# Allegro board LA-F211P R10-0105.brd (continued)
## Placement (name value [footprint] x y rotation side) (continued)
PL606  HCB2012KF-121T50_0805  [TAI-T_HCB2012KF-121T50_2P]  59.12 105.24 0 top
PL607  1UH_MMD-05CZ-1R0M-M7L_7A_20%  [MAGLA_MMD-05CZ-1R0M-M7L_2P]  70.41 104.86 0 bottom
PL608  HCB2012KF-121T50_0805  [TAI-T_HCB2012KF-121T50_2P]  132.04 23.26 180 bottom
PL609  HCB2012KF-121T50_0805  [TAI-T_HCB2012KF-121T50_2P]  59.53 74.39 90 bottom
PL700  HCB2012KF-121T50_0805  [TAI-T_HCB2012KF-121T50_2P]  6.82 55.5 270 bottom
PL701  1UH_MLD-06CZH1R0M-N1L_11.3A_20%  [MAG_MLD-06CZH1R0M-N1L_2P]  11.76 45.91 270 bottom
PL800  1UH_MMD-05CZ-1R0M-M7L_7A_20%  [MAGLA_MMD-05CZ-1R0M-M7L_2P]  81.09 99.81 54.9 bottom
PL801  HCB2012KF-121T50_0805  [TAI-T_HCB2012KF-121T50_2P]  82.87 91.11 180 bottom
PL900  HCB2012KF-121T50_0805  [TAI-T_HCB2012KF-121T50_2P]  18.56 20.29 0 top
PL901  1UH_HEI322512A-1R0M-Q8_3.7A_20%  [CHILI_HEI322512A-1R0M-Q8_2P]  24.23 20.94 90 top
PL1000  BLM15PX121SN1D_2P  [MURAT_BLM15PX121SN1D_2P]  98.75 28.75 270 top
PL1001  1UH_MMD-05CZ-1R0M-M7L_7A_20%  [MAGLA_MMD-05CZ-1R0M-M7L_2P]  102.78 38.67 90 bottom
PL1200  0.15UH_HPPC06030-R15M-Q8_35A_20%  [L_7X7X3_M]  115.93 40.3 90 bottom
PL1201  HCB2012KF-121T50_0805  [TAI-T_HCB2012KF-121T50_2P]  137.45 31.5 180 bottom
PL1202  HCB2012KF-121T50_0805  [TAI-T_HCB2012KF-121T50_2P]  137.45 33.28 180 bottom
PL1203  0.15UH_HPPC06030-R15M-Q8_35A_20%  [L_7X7X3_M]  123.49 40.28 90 bottom
PL1204  0.15UH_HPPC06030-R15M-Q8_35A_20%  [L_7X7X3_M]  131.05 41.85 90 bottom
PL1300  HCB2012KF-121T50_0805  [TAI-T_HCB2012KF-121T50_2P]  151.24 47.21 90 bottom
PL1301  0.15UH_HPPC06030-R15M-Q8_35A_20%  [L_7X7X3_M]  144.05 54.08 180 bottom
PL1302  HCB2012KF-121T50_0805  [TAI-T_HCB2012KF-121T50_2P]  149.44 47.21 90 bottom
PL1303  0.15UH_HPPC06030-R15M-Q8_35A_20%  [L_7X7X3_M]  144.42 64.86 180 bottom
PL1304  HCB2012KF-121T50_0805  [TAI-T_HCB2012KF-121T50_2P]  107.25 32.01 90 bottom
PL1305  0.33UH_MMD-05CZ-R33M-V1L_13.7A_20%  [MAG_MMD-05CZ-R33M-V1L_2P]  109.32 40.96 90 bottom
PL1500  HCB2012KF-121T50_0805  [TAI-T_HCB2012KF-121T50_2P]  70.57 80.55 270 bottom
PL1501  1UH_HEI322512A-1R0M-Q8_3.7A_20%  [CHILI_HEI322512A-1R0M-Q8_2P]  66.62 76.46 180 bottom
PL1900  HCB2012KF-121T50_0805  [TAI-T_HCB2012KF-121T50_2P]  104.73 33.43 180 bottom
PL1901  HCB2012KF-121T50_0805  [TAI-T_HCB2012KF-121T50_2P]  104.74 31.63 180 bottom
PL1902  0.22UH_MMD-06DZER22MEM2L__32A_20%  [L_7X7X4_M]  87.17 41.35 90 bottom
PL1904  0.22UH_MMD-06DZER22MEM2L__32A_20%  [L_7X7X4_M]  71.08 41.39 90 bottom
PL2001  0.22UH_MMD-06DZER22MEM2L__32A_20%  [L_7X7X4_M]  79.18 41.39 90 bottom
PL2200  HCB2012KF-121T50_0805  [TAI-T_HCB2012KF-121T50_2P]  54.66 62.9 0 top
PL2201  0.33UH 20% MMD-05CZ-R33MER1L 13.7A  [MAG_MMD05CZR47M_4P]  64.6 58.76 0 bottom
PL2202  0.22UH_MMD-06DZER22MEM2L__32A_20%  [L_7X7X4_M]  95.91 41.33 90 bottom
PL2203  1UH_HEI322512A-1R0M-Q8_3.7A_20%  [CHILI_HEI322512A-1R0M-Q8_2P]  68.09 51.3 0 bottom
PL2204  HCB2012KF-121T50_0805  [TAI-T_HCB2012KF-121T50_2P]  64.15 52.71 270 top
PL2205  HCB2012KF-121T50_0805  [TAI-T_HCB2012KF-121T50_2P]  145.44 94.1 270 bottom
PL2207  1UH_MMD-05AB-1R0M-V1L_4.4A_20%  [MAG_MMD-05AB-1R0M-V1L_2P]  148.74 85.94 270 bottom
PQ100  AON7401_DFN8-5  [AON7405_DFN8-5]  16.61 74.8 0 bottom
PQ101  S TR AO7401 1P SC70-3  [SI1303DL-T1-E3_SOT323-3]  21.04 77.35 90 top
PQ102  -  [AON7405_DFN8-5]  13.69 70.07 0 bottom
PQ103  -  [AON7405_DFN8-5]  19.59 64.84 180 bottom
PQ105  S TR AO7401 1P SC70-3  [SI1303DL-T1-E3_SOT323-3]  23.53 77.84 180 top
PQ106  S TR AO7401 1P SC70-3  [SI1303DL-T1-E3_SOT323-3]  24.13 71.44 270 top
PQ111  AON7401_DFN8-5  [AON7405_DFN8-5]  22.35 99.87 90 bottom
PQ112  S TR AO7401 1P SC70-3  [SI1303DL-T1-E3_SOT323-3]  22.26 96.67 180 top
PQ113  -  [AON7405_DFN8-5]  22.35 96.06 90 bottom
PQ114  -  [AON7405_DFN8-5]  24.33 94.23 270 bottom
PQ116  S TR AO7401 1P SC70-3  [SI1303DL-T1-E3_SOT323-3]  19.34 100.06 0 top
PQ117  S TR AO7401 1P SC70-3  [SI1303DL-T1-E3_SOT323-3]  26.29 91.43 0 top
PQ132  -  [L2N7002WT1G_SC70-3]  39.72 98.28 180 bottom
PQ133  -  [L2N7002WT1G_SC70-3]  37.16 98.34 180 bottom
PQ134  -  [L2N7002WT1G_SC70-3]  17.92 74.03 180 top
PQ136  -  [2N7002KDW_SOT363-6]  28.89 70.63 90 top
PQ137  -  [L2N7002WT1G_SC70-3]  39.95 94.77 0 top
PQ139  -  [2N7002KDW_SOT363-6]  37.1 95.33 90 top
PQ143  -  [L2N7002WT1G_SC70-3]  22.21 74.79 180 top
PQ144  -  [L2N7002WT1G_SC70-3]  19.61 95.23 180 top
PQ146  -  [2N7002KDW_SOT363-6]  30.52 102.11 90 bottom
PQ147  -  [2N7002KDW_SOT363-6]  35.29 104.03 180 bottom
PQ149  -  [2N7002KDW_SOT363-6]  34.39 100.17 270 top
PQ150  -  [2N7002KDW_SOT363-6]  30.56 106.51 0 bottom
PQ152  -  [2N7002KDW_SOT363-6]  42.01 104.4 0 top
PQ153  -  [2N7002KDW_SOT363-6]  35.21 99.41 270 bottom
PQ154  -  [2N7002KDW_SOT363-6]  31.66 96.9 90 top
PQ155  -  [2N7002KDW_SOT363-6]  27.34 76.23 270 top
PQ199  -  [L2N7002WT1G_SC70-3]  33.54 72.45 90 top
PQ200  PJC138K_SOT-323  [RJU003N03_UMT3]  34.26 96.83 180 bottom
PQ201  PJC138K_SOT-323  [RJU003N03_UMT3]  36.8 96.83 180 bottom
PQ202  PJC138K_SOT-323  [RJU003N03_UMT3]  39.34 96.83 180 bottom
PQ203  PJC138K_SOT-323  [RJU003N03_UMT3]  45.84 96.81 180 top
PQ204  PJC138K_SOT-323  [RJU003N03_UMT3]  43.3 97.59 180 top
PQ205  PJC138K_SOT-323  [RJU003N03_UMT3]  45.2 100.95 90 top
PQ213  -  [L2N7002WT1G_SC70-3]  38.2 103.9 0 top
PQ216  -  [2N7002KDW_SOT363-6]  19.77 69.74 0 top
PQ217  -  [2N7002KDW_SOT363-6]  22.16 91.02 0 top
PQ322  -  [L2N7002WT1G_SC70-3]  49.67 72.47 270 top
PQ325  S TR AO7401 1P SC70-3  [SI1303DL-T1-E3_SOT323-3]  47.41 65.97 270 top
PQ328  S TR AO7401 1P SC70-3  [SI1303DL-T1-E3_SOT323-3]  47.98 68.15 0 top
PQ330  -  [2N7002KDW_SOT363-6]  50.07 68.03 0 top
PQ500  -  [AON7405_DFN8-5]  142.86 4.02 270 bottom
PQ501  -  [L2N7002WT1G_SC70-3]  36.73 3.84 0 top
PQ502  AON6314_DFN5X6-8  [AON6232A_DFN5X6-8-5]  135.18 15.63 90 bottom
PQ503  AON6314_DFN5X6-8  [AON6232A_DFN5X6-8-5]  137.03 13.37 0 bottom
PQ504  -  [AON6380_DFN5X6-8-5]  155.04 18.86 0 bottom
PQ505  -  [AON6380_DFN5X6-8-5]  149.01 16.98 0 bottom
PQ506  AON6314_DFN5X6-8  [AON6232A_DFN5X6-8-5]  146.74 11.65 180 bottom
PQ2200  -  [AON6962_DFN5X6D-8-7]  62.14 62.86 180 top
PR100  300K_0201_1%  [R_0201]  18.32 76.43 90 top
PR101  1M_0201_1%  [R_0201]  20.68 75.09 90 top
PR102  300K_0201_1%  [R_0201]  18.32 77.7 90 top
PR104  100K_0201_1%  [R_0201]  21.5 76.31 270 top
PR105  300K_0201_1%  [R_0201]  20.04 73.97 270 top
PR106  300K_0201_1%  [R_0201]  25.49 73.84 270 top
PR107  1M_0201_1%  [R_0201]  14.79 72.9 180 top
PR108  499K_0402_1%  [R_0402]  25.42 76.41 0 top
PR109  499K_0402_1%  [R_0402]  24.79 74.19 180 top
PR110  0_0402_5%  [R0402_0OHM]  22.91 71.84 180 top
PR112  49.9K_0402_1%  [R_0402]  23.87 74.99 0 top
PR113  300K_0201_1%  [R_0201]  26.03 69.61 0 top
PR114  300K_0201_1%  [R_0201]  19.47 73.39 90 top
PR116  200K _0201_1%  [R_0201]  29.09 72.79 180 top
PR118  49.9K_0402_1%  [R_0402]  27.71 77.3 0 top
PR119  0_0402_5%  [R0402_0OHM]  30.18 74.95 0 top
PR120  0_0402_5%  [R0402_0OHM]  18.34 71.08 180 top
PR121  1M_0201_1%  [R_0201]  30.71 74.27 180 top
PR122  0_0201_5%  [R0201_0OHM]  29.35 74.06 180 top
PR123  0_0402_5%  [R_0402]  26.16 73.41 90 top
PR125  0_0201_5%  [R0201_0OHM]  31.53 100.83 270 top
PR126  1M_0201_1%  [R_0201]  27.82 72.79 180 top
PR127  300K_0201_1%  [R_0201]  20.52 98.04 270 top
PR128  1M_0201_1%  [R_0201]  25.17 95.17 90 top
PR129  300K_0201_1%  [R_0201]  20.52 96.77 270 top
PR131  100K_0201_1%  [R_0201]  25.8 95.75 270 top
PR132  300K_0201_1%  [R_0201]  17.65 100.32 90 top
PR133  300K_0201_1%  [R_0201]  25.68 94.21 0 top
PR135  1M_0201_1%  [R_0201]  18.13 94.74 270 bottom
PR136  0_0402_5%  [R0402_0OHM]  19.61 92.28 180 top
PR137  499K_0402_1%  [R_0402]  19.74 96.87 90 top
PR138  499K_0402_1%  [R_0402]  24.44 90.96 90 top
PR140  49.9K_0402_1%  [R_0402]  29.92 99.23 0 top
PR141  300K_0201_1%  [R_0201]  28.04 93.22 270 top
PR142  300K_0201_1%  [R_0201]  17.65 101.56 90 top
PR143  0_0402_5%  [R0402_0OHM]  30.32 99.99 90 top
PR144  49.9K_0402_1%  [R_0402]  24.76 97.05 0 top
PR145  200K _0201_1%  [R_0201]  38.11 96.88 270 top
PR147  1M_0201_1%  [R_0201]  29.64 100.58 270 top
PR151  0_0402_5%  [R_0402]  33.17 96.48 0 top
PR152  200K _0201_1%  [R_0201]  33.33 101.3 0 bottom
PR153  0_0402_5%  [R0402_0OHM]  33.63 102.14 270 top
PR155  1M_0201_1%  [R_0201]  34.05 97.24 180 top
PR156  200K _0201_1%  [R_0201]  32.86 101.64 90 top
PR157  0_0201_5%  [R0201_0OHM]  34.6 101.3 0 bottom
PR158  0_0402_5%  [R0402_0OHM]  28.63 103.03 270 bottom
PR159  0_0402_5%  [R0402_0OHM]  33.74 102.13 0 bottom
PR160  0_0201_5%  [R0201_0OHM]  35.53 103.05 270 bottom
PR161  0_0402_5%  [R0402_0OHM]  33.74 103.02 0 bottom
PR162  0_0402_5%  [R0402_0OHM]  40.99 105.19 180 top
PR163  0_0402_5%  [R0402_0OHM]  29.5 103.98 270 bottom
PR164  0_0402_5%  [R0402_0OHM]  33.37 98.81 90 top
PR165  0_0402_5%  [R0402_0OHM]  29.5 104.84 90 bottom
PR166  221K_0402_1%  [R_0402]  27.09 97.06 0 top
PR167  1M_0201_1%  [R_0201]  31.66 91.2 0 top
PR168  0_0402_5%  [R0402_0OHM]  33.84 94.35 270 top
PR169  499K_0201_1%  [R_0201]  30.39 91.2 0 top
PR170  1M_0201_1%  [R_0201]  28.08 74 180 top
PR171  499K_0201_1%  [R_0201]  35.53 105.01 90 top
PR172  221K_0402_1%  [R_0402]  35.91 103.92 270 top
PR173  1M_0201_1%  [R_0201]  34.13 106.47 90 top
PR174  0_0402_5%  [R0402_0OHM]  28.33 104.1 0 top
PR175  1M_0201_1%  [R_0201]  31.53 99.56 0 top
PR178  200K _0201_1%  [R_0201]  32.83 100.48 0 top
PR179  200K _0201_1%  [R_0201]  29.66 106.51 180 bottom
PR182  200K _0201_1%  [R_0201]  29.27 92.58 270 top
PR183  200K_0402_1%  [R_0402]  28 96.17 270 top
PR184  200K _0201_1%  [R_0201]  34.9 105.59 270 top
PR185  200K_0402_1%  [R_0402]  35.02 103 90 top
PR186  0_0402_5%  [R0402_0OHM]  37.18 100.44 270 top
PR187  0_0402_5%  [R0402_0OHM]  32.93 104.53 90 bottom
PR188  0_0201_5%  [R0201_0OHM]  36.64 101.24 0 bottom
PR189  0_0201_5%  [R0201_0OHM]  39.43 101.24 0 bottom
PR192  0_0402_5%  [R0402_0OHM]  41.02 106.87 270 top
PR193  0_0402_5%  [R0402_0OHM]  34.52 101.22 90 top
PR195  0_0402_5%  [R0402_0OHM]  42.66 102.46 90 top
PR196  0_0402_5%  [R0402_0OHM]  36.08 97.73 180 top
PR202  200K _0201_1%  [R_0201]  41.96 103.43 270 top
PR203  200K _0201_1%  [R_0201]  32.17 100.25 90 top
PR209  0_0402_5%  [R0402_0OHM]  39.86 106.04 90 top
PR212  0_0402_5%  [R0402_0OHM]  34.72 100.48 180 bottom
PR216  100_0201_1%  [R_0201]  127.23 17.77 270 top
PR217  100_0201_1%  [R_0201]  126.53 17.77 270 top
PR218  100_0201_1%  [R_0201]  125.32 17.77 270 top
PR219  100K_0402_1%  [R_0402]  124.49 17.28 90 top
PR230  1M_0402_1%  [R_0402]  135.56 9.48 180 bottom
PR233  47K_0402_1%  [R_0402]  34.98 106.28 90 top
PR234  47K_0402_1%  [R_0402]  34.08 95.59 180 top
PR237  0_0201_5%  [R0201_0OHM]  44.21 100.17 90 top
PR238  0_0201_5%  [R0201_0OHM]  43.63 100.17 90 top
PR239  0_0201_5%  [R0201_0OHM]  45.55 99.38 0 top
PR240  0_0201_5%  [R0201_0OHM]  35.51 94.25 180 bottom
PR241  0_0201_5%  [R0201_0OHM]  36.76 94.25 0 bottom
PR242  0_0201_5%  [R0201_0OHM]  39.05 94.25 0 bottom
PR246  100K_0201_1%  [R_0201]  32.19 73.99 90 top
PR247  0_0201_5%  [R0201_0OHM]  30.1 71.52 0 top
PR248  100K_0201_1%  [R_0201]  30.68 72.15 180 top
PR249  0_0201_5%  [R0201_0OHM]  30.68 72.79 180 top
PR254  100K_0201_1%  [R_0201]  31.56 101.49 0 top
PR255  0_0201_5%  [R0201_0OHM]  36.51 105.09 90 top
PR256  0_0201_5%  [R0201_0OHM]  38.85 106.74 90 top
PR257  100K_0201_1%  [R_0201]  37.47 106.74 90 top
PR258  0_0402_5%  [R0402_0OHM]  41.65 97.44 270 top
PR263  200K _0201_1%  [R_0201]  18.09 70.36 0 top
PR264  0_0402_5%  [R_0402]  20.49 72.66 180 top
PR265  200K _0201_1%  [R_0201]  23.53 90.06 180 top
PR266  0_0402_5%  [R_0402]  21.97 93.86 0 top
PR267  0_0201_5%  [R0201_0OHM]  43.68 107.02 0 top
PR268  1M_0201_1%  [R_0201]  48.5 105.53 0 top
PR269  0_0201_5%  [R0201_0OHM]  41.51 101.22 90 top
PR270  1M_0201_1%  [R_0201]  40 103.54 0 top
PR271  0_0201_5%  [R0201_0OHM]  38.45 97.76 0 top
PR272  1M_0201_1%  [R_0201]  40.24 97.8 0 top
PR273  0_0201_5%  [R0201_0OHM]  43.75 102.86 90 top
PR274  1M_0201_1%  [R_0201]  48.13 102.76 0 top
PR275  0_0402_5%  [R0402_0OHM]  44.27 105.23 90 top
PR276  0_0402_5%  [R0402_0OHM]  43.27 101.68 0 top
PR354  0_0805_5%  [R0805_0OHM]  46.57 69.71 0 bottom
PR363  300K_0402_5%  [R_0402]  43.6 68.46 90 bottom
PR367  300K_0402_5%  [R_0402]  48.55 71.91 270 top
PR375  1M_0402_1%  [R_0402]  48.85 63.21 0 top
PR378  10K_0402_1%  [R_0402]  47.98 64.09 180 top
PR383  0_0805_5%  [R0805_0OHM]  51.15 63.96 270 top
PR384  100K_0402_1%  [R_0402]  50.57 65.91 270 top
PR389  0_0402_5%  [R0402_0OHM]  50.53 66.87 0 top
PR392  0_0402_5%  [R0402_0OHM]  49.86 70.77 0 top
PR500  0.01_1206_1%  [R_1206_4P-D]  148.94 2.77 180 bottom
PR501  442K_0402_1%  [R_0402]  163.31 2.05 180 top
PR502  2.2_0603_1%  [R_0603]  154.53 7.51 0 top
PR503  2.2_0603_1%  [R_0603]  154.53 8.73 0 top
PR504  100K_0201_1%  [R_0201]  160.44 2.96 90 top
PR505  2.2_0603_5%  [R_0603]  157.77 8.11 0 bottom
PR506  2_1206_5%  [R_1206]  154.75 5 0 top
PR507  4.7_0402_5%  [R_0402]  158.9 10.53 90 top
PR508  2_1206_5%  [R_1206]  154.75 3.02 0 top
PR509  0_0201_5%  [R_0201]  162.24 2.88 0 top
PR510  2.2_0603_5%  [R_0603]  160.84 11.89 0 bottom
PR511  0.005_1206_1%  [R_1206_4P-D]  138.49 5.92 0 bottom
PR512  0_0201_5%  [R0201_0OHM]  163.42 2.84 90 top
PR513  0_0402_5%  [R0402_0OHM]  164.18 2.04 90 top
PR514  0_0402_5%  [R0402_0OHM]  165.07 2.04 90 top
PR515  75_0402_5%  [R_0402]  165.96 2.04 90 top
PR516  0_0402_5%  [R0402_0OHM]  161.59 13.29 180 top
PR517  100K_0402_1%  [R_0402]  168.88 2.36 0 top
PR518  154K_0402_1%  [R_0402]  38.48 3.84 270 top
PR519  4.7_1206_5%  [R_1206]  154.78 18.31 0 top
PR520  4.7_1206_5%  [R_1206]  138.53 15.45 90 top
PR521  1_0201_1%  [R_0201]  163.34 13.24 270 top
PR522  1_0201_1%  [R_0201]  163.93 13.24 270 top
PR524  105K_0402_1%  [R_0402]  167.34 5.48 0 top
PR525  0_0201_5%  [R0201_0OHM]  167.7 4.79 180 top
PR526  0_0201_5%  [R0201_0OHM]  168.51 8.57 0 top
PR527  0_0402_5%  [R0402_0OHM]  167.34 6.5 0 top
PR529  10K_0402_5%  [R_0402]  169.08 7.88 0 top
PR530  100_0402_1%  [R_0402]  166.86 8.59 90 top
PR536  0_0201_5%  [R0201_0OHM]  53.37 1.54 90 top
PR537  0_0201_5%  [R0201_0OHM]  54.01 1.54 90 top
PR538  1K_0402_1%  [R_0402]  167.36 7.51 0 top
PR539  1M_0201_1%  [R_0201]  169.49 3.32 180 top
PR540  100K_0402_1%  [R_0402]  169.91 4.08 180 top
PR541  1M_0201_1%  [R_0201]  38.48 5.2 270 top
PR542  0_0402_5%  [R0402_0OHM]  167.79 3.07 180 top
PR543  0_0402_5%  [R0402_0OHM]  50.43 106.09 270 top
PR544  0_0402_5%  [R0402_0OHM]  49.39 102.83 0 top
PR545  0_0402_5%  [R0402_0OHM]  34.72 4.69 270 top
PR546  0_0402_5%  [R0402_0OHM]  30.59 5.44 0 top
PR547  100K_0201_1%  [R_0201]  31.51 6.14 0 top
PR548  0_0402_5%  [R0402_0OHM]  49.36 101.76 0 top
PR549  0_0402_5%  [R0402_0OHM]  49.32 104.04 0 top
PR550  2.2_1206_1%  [R_1206]  154.91 11.27 0 top
PR551  2.2_1206_1%  [R_1206]  156.66 16.06 0 top
PR552  1M_0402_1%  [R_0402]  34.32 2.11 90 top
PR553  0_0402_5%  [R0402_0OHM]  165.38 12.08 180 bottom
PR554  0_0402_5%  [R_0402]  33.16 5.44 180 top
PR555  100K_0402_1%  [R_0402]  35.1 3.03 270 top
PR600  0_0402_5%  [R0402_0OHM]  13.26 20.78 180 bottom
PR601  3.3_0603_1%  [R_0603]  14.26 24.21 0 bottom
PR602  4.7_0805_5%  [R_0805]  10 24.21 0 top
PR604  0_0402_5%  [R0402_0OHM]  15.8 22.18 180 bottom
PR605  2.2K_0402_1%  [R_0402]  15.8 23.07 180 bottom
PR606  1M_0201_1%  [R_0201]  14.07 22.65 90 bottom
PR607  0_0402_5%  [R_0402]  60.4 78.84 180 bottom
PR608  3.3_0603_1%  [R_0603]  59.54 82.27 0 bottom
PR609  4.7_0805_5%  [R_0805]  56.51 80.92 180 top
PR610  100K_0402_5%  [R_0402]  53.11 79.83 180 bottom
PR611  0_0402_5%  [R0402_0OHM]  60.64 80.7 270 bottom
PR612  100K_0201_1%  [R_0201]  61.41 80.05 90 bottom
PR613  0_0402_5%  [R_0402]  128.63 27.58 180 bottom
PR614  3.3_0603_1%  [R_0603]  126.02 28.15 180 bottom
PR615  4.7_0805_5%  [R_0805]  125.17 22.68 90 top
PR616  100K_0402_5%  [R_0402]  126.22 20.96 180 bottom
PR617  0_0402_5%  [R0402_0OHM]  128.63 28.4 180 bottom
PR618  100K_0201_1%  [R_0201]  126.84 27.86 90 bottom
PR619  0_0402_5%  [R0402_0OHM]  62.25 107.22 270 top
PR620  3.3_0603_1%  [R_0603]  66.52 105.43 90 top
PR621  4.7_0805_5%  [R_0805]  66.77 102.95 270 top
PR622  100K_0402_5%  [R_0402]  63.03 99.71 0 top
PR623  0_0402_5%  [R0402_0OHM]  63.03 107.22 270 top
PR624  0_0201_5%  [R0201_0OHM]  6.41 22.84 90 bottom
PR625  100K_0201_1%  [R_0201]  63.79 106.57 90 top
PR626  0_0201_5%  [R0201_0OHM]  52.81 79.04 180 bottom
PR627  0_0201_5%  [R0201_0OHM]  127 20.96 0 bottom
PR628  100K_0402_5%  [R_0402]  7.11 23.92 270 bottom
PR629  0_0201_5%  [R0201_0OHM]  60.68 100.48 180 top
PR700  4.7_0805_5%  [R_0805]  11.27 47.94 90 top
PR701  0_0402_5%  [R_0402]  7.2 49.1 180 bottom
PR702  14K_0402_1%  [R_0402]  14.33 50.37 180 bottom
PR703  100K_0402_1%  [R_0402]  14.08 55.1 180 bottom
PR704  1M_0201_1%  [R_0201]  12.39 55.84 180 bottom
PR705  20K_0402_1%  [R_0402]  13.48 52.25 0 bottom
PR706  0_0402_5%  [R_0402]  14.18 54.16 180 bottom
PR707  0_0402_5%  [R_0402]  13.27 53.24 0 bottom
PR708  0_0402_5%  [R0402_0OHM]  11.39 54.12 0 bottom
PR800  2.2_0603_5%  [R_0603]  83.19 97.31 54.3 bottom
PR801  4.7_0805_5%  [R_0805]  79.47 99.87 270 top
PR802  75_0402_5%  [R_0402]  83.17 96.12 180 bottom
PR803  100K_0402_1%  [R_0402]  80.86 97.5 270 top
PR804  100K_0402_1%  [R_0402]  81.58 95.65 180 top
PR805  0_0402_5%  [R0402_0OHM]  78.38 94.7 0 top
PR806  100K_0402_5%  [R_0402]  73.49 90.63 0 bottom
PR808  1M_0201_1%  [R_0201]  80.07 94.7 0 top
PR809  150K_0402_1%  [R_0402]  82.2 94.34 0 bottom
PR810  0_0402_5%  [R0402_0OHM]  76.12 90.63 180 bottom
PR811  0_0402_5%  [R0402_0OHM]  77 96.77 270 top
PR812  1M_0201_1%  [R_0201]  79.43 97.17 0 top
PR813  10K_0402_1%  [R_0402]  79.02 96.35 0 top
PR814  0_0402_5%  [R0402_0OHM]  79.02 95.59 0 top
PR900  0_0402_5%  [R_0402]  15.9 25.55 270 top
PR901  100K_0402_5%  [R_0402]  14.88 22.94 0 top
PR902  1M_0201_5%  [R_0201]  16.61 24.87 90 top
PR903  4.7_0603_5%  [R_0603]  21.94 21.04 90 top
PR904  100K_0402_1%  [R_0402]  19.29 24.85 180 top
PR905  133K_0402_1%  [R_0402]  18.31 26.75 0 top
PR906  0_0402_5%  [R_0402]  17.24 20.66 180 top
PR907  0_0402_5%  [R_0402]  14.88 22.18 0 top
PR1000  4.7_0805_5%  [R_0805]  101.24 31.62 180 top
PR1001  0_0402_5%  [R_0402]  100.1 28.53 90 top
PR1002  0_0402_5%  [R0402_0OHM]  102.23 23.77 180 top
PR1003  47K_0402_1%  [R_0402]  103.59 23.74 0 top
PR1004  100_0402_1%  [R_0402]  107.98 26.55 90 top
PR1006  0_0402_5%  [R0402_0OHM]  109.61 28.33 90 top
PR1007  36.5K_0402_1%  [R_0402]  107.11 27.45 180 top
PR1008  0_0402_5%  [R_0402]  108.12 25.61 180 top
PR1009  62K_0402_1%  [R_0402]  106.19 28.34 0 top
PR1010  0_0402_5%  [R_0402]  107.21 24.72 0 top
PR1011  0_0402_5%  [R0402_0OHM]  108.81 28.33 90 top
PR1012  100_0402_1%  [R_0402]  107.98 28.33 90 top
PR1013  100K_0402_5%  [R_0402]  104.5 24.53 180 top
PR1100  2M_0402_5%  [R_0402]  134.65 32.77 90 top
PR1101  0_0402_5%  [R_0402]  146.72 46.01 270 top
PR1102  4.7_0402_5%  [R_0402]  135.4 42.12 0 top
PR1103  133K_0402_1%  [R_0402]  135.54 33.69 270 top
PR1104  1.91K_0402_1%  [R_0402]  141.5 46.07 270 top
PR1105  10K_0402_1%  [R_0402]  139.35 46.64 270 top
PR1106  10K_0402_1%  [R_0402]  138.53 46.64 270 top
PR1107  10K_0402_1%  [R_0402]  136.12 48.8 270 top
PR1108  10K_0402_1%  [R_0402]  135.28 43.96 0 top
PR1109  0_0402_5%  [R0402_0OHM]  135.28 43.07 0 top
PR1110  0_0402_5%  [R_0402]  137.19 46.2 270 top
PR1111  45.3_0402_1%  [R_0402]  145.39 50.2 270 top
PR1112  100_0402_1%  [R_0402]  144.24 50.2 270 top
PR1113  0_0603_5%  [R0603_0OHM]  137.51 48.98 270 top
PR1114  0_0603_5%  [R0603_0OHM]  139.35 48.98 270 top
PR1115  10K_0402_1%  [R_0402]  140.94 49.24 270 top
PR1116  75_0402_1%  [R_0402]  143.35 50.2 270 top
PR1117  1.5K_0402_1%  [R_0402]  140.88 34.38 270 top
PR1118  1.5K_0402_1%  [R_0402]  139.99 34.38 270 top
PR1119  1.5K_0402_1%  [R_0402]  139.1 33.69 270 top
PR1120  0_0402_5%  [R0402_0OHM]  140.37 47.28 270 top
PR1121  1.5K_0402_1%  [R_0402]  138.21 33.69 270 top
PR1122  0_0402_5%  [R0402_0OHM]  141.89 47.97 270 top
PR1123  1.5K_0402_1%  [R_0402]  137.32 33.69 270 top
PR1124  0_0402_5%  [R0402_0OHM]  144.94 48.1 270 top
PR1125  49.9_0402_1%  [R_0402]  143.86 46.07 270 top
PR1126  1.5K_0402_1%  [R_0402]  136.43 33.69 270 top
PR1127  0_0402_5%  [R0402_0OHM]  142.78 47.97 270 top
PR1128  0_0402_5%  [R0402_0OHM]  142.29 46.07 270 top
PR1129  0_0402_5%  [R0402_0OHM]  143.76 47.96 270 top
PR1130  10_0402_1%  [R_0402]  143.07 46.07 270 top
PR1131  1.43K_0402_1%  [R_0402]  141.77 34.38 270 top
PR1132  0_0402_5%  [R0402_0OHM]  149.53 44.72 180 top
PR1133  10K_0402_1%  [R_0402]  147.67 45.62 270 top
PR1134  5.23K_0402_1%  [R_0402]  135.15 35.07 0 top
PR1135  100K_0402_1%  [R_0402]  139.11 31.39 180 top
PR1136  0_0402_5%  [R0402_0OHM]  135.15 36.85 0 top
PR1137  0_0402_5%  [R0402_0OHM]  142.85 34.38 270 top
PR1138  0_0402_5%  [R0402_0OHM]  136.12 46.7 270 top
PR1139  61.9K_0402_1%  [R_0402]  148.38 43.83 180 top
PR1140  0_0402_5%  [R0402_0OHM]  143.74 34.38 270 top
PR1141  10K_0402_1%  [R_0402]  135.4 44.91 0 top
PR1142  2.1K_0402_1%  [R_0402]  144.62 34.38 270 top
PR1143  54.9K_0402_1%  [R_0402]  150.1 40.6 180 top
PR1144  100K_0402_1%  [R_0402]  145.51 34.38 270 top
PR1145  0_0402_5%  [R0402_0OHM]  146.39 34.75 0 top
PR1146  68K_0402_1%  [R_0402]  150.1 41.67 180 top
PR1147  0_0402_5%  [R0402_0OHM]  146.39 35.71 0 top
PR1148  332K_0402_1%  [R_0402]  150.1 42.75 180 top
PR1149  0_0402_5%  [R0402_0OHM]  135.15 38.63 0 top
PR1150  0_0402_5%  [R0402_0OHM]  147.47 38.69 0 top
PR1151  8.06K_0402_1%  [R_0402]  146.53 36.84 90 top
PR1152  49.9K_0402_1%  [R_0402]  136.06 37.74 180 top
PR1153  0_0402_5%  [R0402_0OHM]  147.47 39.64 0 top
PR1154  100K_0402_1%  [R_0402]  147.47 37.74 0 top
PR1200  0_0402_5%  [R0402_0OHM]  112.67 38.26 270 top
PR1201  4.7_1206_5%  [R_1206]  114.22 42.48 0 top
PR1202  0_0402_5%  [R0402_0OHM]  119.86 38 270 top
PR1203  4.7_1206_5%  [R_1206]  121.96 42.87 0 top
PR1204  0_0402_5%  [R0402_0OHM]  127.16 39.53 270 top
PR1205  4.7_1206_5%  [R_1206]  128.64 43.77 0 top
PR1300  0_0402_5%  [R0402_0OHM]  147.68 53.04 180 top
PR1301  4.7_1206_5%  [R_1206]  143.18 57.07 90 top
PR1302  0_0402_5%  [R0402_0OHM]  148.38 62.88 180 top
PR1303  4.7_1206_5%  [R_1206]  142.78 63.07 90 top
PR1304  0_0402_5%  [R0402_0OHM]  106.68 39.37 270 top
PR1305  4.7_1206_5%  [R_1206]  108.62 40.09 90 top
PR1500  0_0402_5%  [R0402_0OHM]  70.66 84.16 180 bottom
PR1502  1M_0201_5%  [R_0201]  69.78 83.39 0 bottom
PR1503  4.7_0603_5%  [R_0603]  68.07 75.32 0 bottom
PR1504  40.2K_0402_1%  [R_0402]  66.56 82.43 0 bottom
PR1505  20K_0402_1%  [R_0402]  67.66 83.32 90 bottom
PR1506  0_0402_5%  [R0402_0OHM]  68.93 79.72 270 top
PR1507  0_0402_5%  [R0402_0OHM]  70.08 82.45 270 bottom
PR1800  10K_0402_5%  [R_0402]  49.51 41.66 180 top
PR1801  10K_0402_5%  [R_0402]  49.51 37.86 180 top
PR1802  2.2_0603_1%  [R_0603]  51.3 28.85 90 top
PR1803  1K_0603_1%  [R_0603]  53.54 26.31 90 top
PR1806  10K_0402_5%  [R_0402]  48.6 40.77 0 top
PR1807  10K_0402_5%  [R_0402]  48.6 39.83 0 top
PR1808  10K_0402_5%  [R_0402]  48.6 38.88 0 top
PR1809  0_0201_5%  [R_0201]  47.56 42.79 270 top
PR1810  0_0402_5%  [R0402_0OHM]  50.39 39.87 90 top
PR1812  15K_0402_1%  [R_0402]  63.65 31.77 0 top
PR1813  0_0402_5%  [R0402_0OHM]  49.3 31.32 0 top
PR1814  10K_0402_1%  [R_0402]  63.65 33.55 0 top
PR1815  0_0402_5%  [R0402_0OHM]  50.38 38.88 0 top
PR1816  0_0402_5%  [R0402_0OHM]  50.38 37.86 0 top
PR1817  10_0402_1%  [R_0402]  63.85 35.58 0 top
PR1818  100K_0402_5%  [R_0402]  62.98 34.68 90 top
PR1819  7.5K_0402_1%  [R_0402]  64.77 34.7 180 top
PR1820  0_0402_5%  [R0402_0OHM]  47.77 36.79 0 top
PR1821  10_0402_1%  [R_0402]  63.65 40.09 0 top
PR1822  100K_0402_5%  [R_0402]  61.88 39.19 90 top
PR1823  0_0402_5%  [R0402_0OHM]  49.3 33.1 0 top
PR1824  7.5K_0402_1%  [R_0402]  64.56 39.2 180 top
PR1825  97.6K_0402_1%  [R_0402]  63.65 32.66 0 top
PR1826  47_0402_5%  [R_0402]  51.79 44.01 90 top
PR1827  12K_0402_1%  [R_0402]  53.76 43.19 90 top
PR1828  10_0402_1%  [R_0402]  63.65 38.31 0 top
PR1829  100K_0402_5%  [R_0402]  62.77 37.41 90 top
PR1830  1K_0402_0.5%  [R_0402]  51.77 43.14 0 top
PR1831  7.5K_0402_1%  [R_0402]  64.56 37.42 180 top
PR1832  10K_0402_1%  [R_0402]  63.65 30.88 0 top
PR1833  562K_0402_1%  [R_0402]  52.69 45.8 180 top
PR1834  10_0402_1%  [R_0402]  62.38 41.93 0 top
PR1835  100_0402_5%  [R_0402]  87.79 53.47 90 bottom
PR1836  100K_0402_5%  [R_0402]  60.6 41.93 0 top
PR1837  7.5K_0402_1%  [R_0402]  61.95 46.23 0 top
PR1838  2K_0402_1%  [R_0402]  63.29 41.04 180 top
PR1839  0_0402_5%  [R_0402]  63.73 46.28 0 top
PR1840  0_0402_5%  [R0402_0OHM]  50.83 47.02 270 top
PR1841  240K_0603_1%  [R_0603]  64.49 44.85 0 top
PR1842  0_0402_5%  [R0402_0OHM]  49.88 47.02 270 top
PR1843  47K_0402_1%  [R_0402]  56.79 44.53 0 top
PR1844  100K_0402_5%  [R_0402]  57.71 45.42 180 top
PR1845  240K_0603_1%  [R_0603]  64.93 43.64 0 top
PR1846  100_0402_5%  [R_0402]  86.97 54.39 270 bottom
PR1847  240K_0603_1%  [R_0603]  64.93 42.44 0 top
PR1848  15K_0402_1%  [R_0402]  55.77 40.98 0 top
PR1849  240K_0603_1%  [R_0603]  60.92 44.77 90 top
PR1850  44.2K_0402_1%  [R_0402]  58.57 42.75 0 top
PR1851  1K_0402_0.5%  [R_0402]  55.77 43.64 0 top
PR1853  100_0402_1%  [R_0402]  56.69 41.87 180 top
PR1854  10_0402_1%  [R_0402]  64.18 36.56 180 bottom
PR1855  10_0402_1%  [R_0402]  64.26 39.91 180 bottom
PR1856  0_0402_5%  [R0402_0OHM]  49.3 33.86 0 top
PR1857  10_0402_1%  [R_0402]  64.23 38.21 180 bottom
PR1858  10_0402_1%  [R_0402]  63.29 42.82 180 top
PR1859  47_0402_5%  [R_0402]  56.57 29.69 270 top
PR1860  5.1K_0402_1%  [R_0402]  54.5 27.08 0 top
PR1861  10K_0402_1%  [R_0402]  63.65 29.99 0 top
PR1862  1K_0402_0.5%  [R_0402]  55.95 30.56 180 top
PR1863  10_0402_1%  [R_0402]  64.56 29.1 180 top
PR1864  562K_0402_1%  [R_0402]  55.42 27.97 180 top
PR1865  100_0402_5%  [R_0402]  73 68.08 90 bottom
PR1866  8.25K_0402_1%  [R_0402]  63.65 28.21 0 top
PR1867  680K_0603_1%  [R_0603]  63.15 27.13 0 top
PR1868  47K_0402_1%  [R_0402]  60.93 27.46 270 top
PR1869  100K_0402_5%  [R_0402]  61.82 26.55 90 top
PR1870  0_0402_5%  [R0402_0OHM]  54.64 28.77 90 top
PR1871  2.67K_0402_1%  [R_0402]  57.17 31.32 0 top
PR1872  33.2K_0402_1%  [R_0402]  59.15 30.38 270 top
PR1875  1K_0402_0.5%  [R_0402]  59.22 26.68 90 top
PR1876  16.2K_0402_1%  [R_0402]  59.23 28.47 180 top
PR1877  0_0402_5%  [R0402_0OHM]  49.68 35.58 0 top
PR1878  0_0402_5%  [R0402_0OHM]  49.68 34.75 0 top
PR1879  60.4K_0402_1%  [R_0402]  52.17 26.93 90 top
PR1880  0_0402_5%  [R_0402]  49.3 30.56 0 top
PR1900  3.9_0603_1%  [R_0603]  87.39 32.56 270 bottom
PR1901  2.2_0603_1%  [R_0603]  90.03 31.22 90 bottom
PR1902  2.2_0805_5%  [R_0805]  88.93 40.38 270 top
PR1903  2.2_0603_1%  [R_0603]  72.7 31.17 90 bottom
PR1904  3.9_0603_1%  [R_0603]  69.94 32.56 270 bottom
PR1905  2.2_0805_5%  [R_0805]  71.92 40.46 270 top
PR2000  3.9_0603_1%  [R_0603]  78.67 32.54 270 bottom
PR2001  2.2_0603_1%  [R_0603]  81.26 31.17 90 bottom
PR2002  2.2_0805_5%  [R_0805]  79.22 40.68 270 top
PR2200  2.2_0603_5%  [R_0603]  55.83 53.2 90 top
PR2201  0_0603_5%  [R0603_0OHM]  58.84 64.19 0 top
PR2202  2.2_0805_5%  [R_0805]  64.17 55.33 180 top
PR2203  2.2_0603_1%  [R_0603]  98.55 31.1 90 bottom
PR2204  3.9_0603_1%  [R_0603]  95.98 32.51 270 bottom
PR2205  2.2_0805_5%  [R_0805]  97.7 40.29 270 top
PR2250  0_0402_5%  [R0402_0OHM]  58.14 50.06 90 top
PR2251  2_0603_5%  [R_0603]  60.99 50.5 180 top
PR2300  0_0603_5%  [R0603_0OHM]  85.92 105.89 270 top
PR2301  100K_0402_1%  [R_0402]  85.15 110.34 90 top
PR2302  21.5K_0402_1%  [R_0402]  86.08 107.57 90 top
PR2303  0_0402_5%  [R0402_0OHM]  80.25 110.36 90 top
PR2304  10K_0402_1%  [R_0402]  85.11 109.56 0 top
PR2305  0_0402_5%  [R0402_0OHM]  84.35 110.34 90 top
PR2306  100_0402_5%  [R_0402]  78.08 108.68 0 top
PR2307  300K_0402_1%  [R_0402]  78.08 109.47 0 top
PR2308  4.7_0603_5%  [R_0603]  65.34 50.16 90 bottom
PR2309  0_0201_5%  [R0201_0OHM]  68 46.17 90 top
PR2311  100_0402_1%  [R_0402]  68.25 53.33 180 top
PR2312  100_0402_1%  [R_0402]  66.32 52.83 180 top
PR2313  34K_0402_1%  [R_0402]  67.95 52.57 270 top
PR2315  0_0201_5%  [R0201_0OHM]  66.36 53.53 180 top
PR2316  0_0201_5%  [R0201_0OHM]  67.18 54.01 0 top
PR2317  10K_0402_5%  [R_0402]  66.4 46.64 0 top
PR2318  1M_0201_5%  [R_0201]  68.57 46.76 270 top
PR2319  66.5K_0402_1%  [R_0402]  67.15 51.66 90 top
PR2320  0_0201_5%  [R0201_0OHM]  65.9 52.11 270 top
PR2321  100K_0201_1%  [R_0201]  65.33 52.11 270 top
PR2328  4.7K_0603_5%  [R_0603]  149.63 85.8 270 top
PR2329  1M_0201_1%  [R_0201]  151.57 92.88 0 bottom
PR2330  0_0402_5%  [R_0402]  145.72 88.98 270 bottom
PR2331  0_0201_5%  [R0201_0OHM]  150.84 92.93 90 bottom
PR2332  0_0201_5%  [R_0201]  151.53 91.06 0 bottom
PR2333  0_0201_5%  [R_0201]  152.11 90.48 180 bottom
PR2334  0_0201_5%  [R0201_0OHM]  152.13 91.68 180 bottom
PR2335  100K_0402_1%  [R_0402]  151.26 89.94 0 top
PR2336  42.2K_0402_1%  [R_0402]  151.08 88.4 0 top
PR2337  0_0402_5%  [R0402_0OHM]  48.6 42.45 0 top
PR2338  100K_0402_5%  [R_0402]  47.84 39.39 90 top
PR2339  100K_0402_5%  [R_0402]  44.16 42.74 270 top
PR2340  0_0402_5%  [R0402_0OHM]  42.26 47.07 270 top
PT100  PAD~D  [TPC12]  28.8 69.36 0 top
PT101  PAD~D  [TPC12]  14.13 104.44 0 top
PT500  PAD~D  [TPC12]  143.16 2.37 180 top
PT501  PAD~D  [TPC12]  39.47 2.52 0 top
PT502  PAD~D  [TPC12]  30.68 2.14 180 top
PU78  -  [MC74VHC1G08DFT2G_SC70-5]  42.26 45.16 270 top
PU100  -  [AS331KTR-G1_SOT23-5]  29.09 95.51 270 top
PU101  -  [AS331KTR-G1_SOT23-5]  32.89 103.4 90 top
PU102  TC7SZ14FU SSOP  [74AUP1G04GW_TSSOP5]  45.53 106.97 270 top
PU300  -  [RT9069-33GB_SOT23-5]  46.65 65.54 180 bottom
PU501  ISL88738HRTZ-T_TQFN32_4X4  [ISL88738HRTZ-T_TQFN32_4X4-S]  164.69 9.05 270 top
PU503  -  [MC74VHC1G08DFT2G_SC70-5]  31.99 2.5 0 top
PU600  -  [NB680GD-Z_QFN12_2X3]  10.66 22.55 90 bottom
PU601  -  [NB679AGD-Z_QFN12_2X3]  57.09 79.63 90 bottom
PU602  -  [NB679AGD-Z_QFN12_2X3]  126.1 24.38 180 bottom
PU603  -  [NB680GD-Z_QFN12_2X3]  63.28 103.6 0 top
PU700  -  [SY8286RAC_QFN20_3X3]  8.63 49.4 0 bottom
PU800  -  [NB685GQ-Z_QFN16_3X3]  79.89 93.94 90 bottom
PU900  -  [SYV659LQWC_QFN7_1P5X1P5]  17.27 23.25 0 top
PU1000  -  [SY8286RAC_QFN20_3X3]  101.61 28.29 0 top
PU1100  MP2949AGQKT-0022-Z_TQFN48_6X6  [MP2949AGQKT-0022-Z_TQFN48_6X6-S]  139.33 36.57 90 top
PU1200  -  [MP86901-CGLT-Z_TQFN21_3X4]  114.82 36.96 270 bottom
PU1201  -  [MP86901-CGLT-Z_TQFN21_3X4]  122.07 36.55 270 bottom
PU1202  -  [MP86901-CGLT-Z_TQFN21_3X4]  129.22 37.95 270 bottom
PU1300  -  [MP86901-CGLT-Z_TQFN21_3X4]  147.23 55.38 0 bottom
PU1301  -  [MP86901-CGLT-Z_TQFN21_3X4]  147.69 65.14 0 bottom
PU1302  -  [MP86901-BGLT-Z_TQFN21_3X4]  107.96 37.91 270 bottom
PU1500  -  [SYV659LQWC_QFN7_1P5X1P5]  67.61 81.08 270 bottom
PU1800  NCP81022MNTXG_QFN52_6X6  [NCP81022MNTXG_QFN52_6X6-S]  53.58 38.33 0 top
PU1900  -  [NCP302045MNTXG_PQFN33_5X5]  89.92 33.88 180 bottom
PU1901  -  [NCP302045MNTXG_PQFN33_5X5]  72.61 33.89 180 bottom
PU2000  -  [NCP302045MNTXG_PQFN33_5X5]  81.17 33.9 180 bottom
PU2200  -  [NCP81151MNTBG_DFN8_2X2]  57.04 52.16 0 top
PU2201  -  [NCP302045MNTXG_PQFN33_5X5]  98.77 33.89 180 bottom
PU2300  -  [RT9059GQW_WDFN10_3X3]  83.75 107.27 90 top
PU2301  TC7SZ14FU SSOP  [74AUP1G04GW_TSSOP5]  40.27 101.34 90 top
PU2302  TC7SZ14FU SSOP  [74AUP1G04GW_TSSOP5]  38.45 99.97 270 top
PU2303  TC7SZ14FU SSOP  [74AUP1G04GW_TSSOP5]  45.01 104.29 270 top
PU2304  -  [SY8286RAC_QFN20_3X3]  147.24 89.32 0 bottom
PU4255  -  [SY8868QMC_QFN10_2X2]  66.51 49.28 0 top
Q3  -  [L2N7002WT1G_SC-70-3]  65.68 18.22 90 top
Q4  -  [L2N7002WT1G_SC-70-3]  6.83 44.09 180 bottom
Q5  -  [L2N7002WT1G_SC-70-3]  85.69 4.77 270 bottom
Q6  -  [L2N7002WT1G_SC-70-3]  3.69 9.06 0 bottom
QC1  -  [DMN65D8LDW-7_SOT363-6]  57.44 65.63 270 bottom
QC2  -  [DMN65D8LDW-7_SOT363-6]  64.02 15.9 180 top
QC3  LMBT3904WT1G SC70-3  [MMBT3904WT1G_SC70-3]  63.42 86.64 180 top
QC6  -  [DMN65D8LDW-7_SOT363-6]  59.35 12.67 270 top
QC7  -  [DMN65D8LDW-7_SOT363-6]  57.39 19.45 180 top
QC123  -  [L2N7002WT1G_SC-70-3]  29.62 23.58 270 top
QC124  -  [L2N7002WT1G_SC-70-3]  18.32 38.12 180 top
QC125  -  [L2N7002WT1G_SC-70-3]  47.88 14.23 270 bottom
QC126  -  [L2N7002WT1G_SC-70-3]  54.75 11.57 0 bottom
QE12  LMBT3904WT1G SC70-3  [MMBT3904WT1G_SC70-3]  106.59 80.47 180 top
QE13  LNTA7002NT1G_SC89-3  [LNTA7002NT1G_SC-89-3]  33.06 18.57 270 top
QE14  LMBT3904WT1G SC70-3  [MMBT3904WT1G_SC70-3]  116.68 107.2 0 bottom
QE16  LMBT3904WT1G SC70-3  [MMBT3904WT1G_SC70-3]  33.81 15.58 90 top
QE20  LMBT3904WT1G SC70-3  [MMBT3904WT1G_SC70-3]  158.62 13.68 90 top
QE21  LMBT3904WT1G SC70-3  [MMBT3904WT1G_SC70-3]  42.45 68.54 0 top
QE22  LMBT3904WT1G SC70-3  [MMBT3904WT1G_SC70-3]  77.44 15.71 180 bottom
QE23  LMBT3904WT1G SC70-3  [MMBT3904WT1G_SC70-3]  34.96 22.62 270 top
QE25  -  [DMN66D0LDW-7_SOT363-6]  68.16 93.37 0 top
QE27  -  [DMN65D8LDW-7_SOT363-6]  45.82 22.61 90 top
QE28  LMBT3904WT1G SC70-3  [MMBT3904WT1G_SC70-3]  96.24 42.5 270 top
QE30  -  [DMN66D0LDW-7_SOT363-6]  60.54 75.01 0 top
QE31  -  [DMN66D0LDW-7_SOT363-6]  58.06 75.01 0 top
QE32  -  [DMN66D0LDW-7_SOT363-6]  49.42 51.77 0 top
QH1  -  [DMN66D0LDW-7_SOT363-6]  7.84 33.31 270 bottom
QH2  -  [DMN66D0LDW-7_SOT363-6]  5.94 35.5 90 bottom
QP1  -  [L2N7002WT1G_SC-70-3]  41.02 66.66 270 bottom
QP2  -  [L2N7002WT1G_SC-70-3]  40.18 69.93 270 bottom
QP3  -  [L2N7002WT1G_SC-70-3]  39.53 67.14 270 top
QP4  -  [L2N7002WT1G_SC-70-3]  38.96 71.14 0 top
QR1  -  [L2N7002WT1G_SC-70-3]  17.69 59.52 0 top
QRTC  -  [LP2301ALT1G_SOT23-3]  68.69 22.82 180 top
QRTC1  DII-DMN65D8LW-7  [DMN65D8LW-7_SOT323-3]  70.47 25.43 270 top
QV8  -  [SI3457CDV-T1-GE3_TSOP6]  63.03 95.1 90 top
QV9  -  [L2N7002WT1G_SC-70-3]  65.54 98.25 90 top
QV10  -  [L2N7002WT1G_SC-70-3]  64.23 102.06 180 bottom
QV11  -  [DMN66D0LDW-7_SOT363-6]  56.28 103.82 180 top
QV12  -  [FDMC6675BZ_MLP8-5]  116.93 17.7 90 top
QV13  LNTA7002NT1G_SC89-3  [2N7002KTB_SOT523-3]  121.59 19.6 90 top
QZ9  -  [DMG2301U-7_SOT23-3]  149.53 102.83 180 top
QZ10  -  [FDMC6675BZ_MLP8-5]  140.02 85.09 0 top
QZ11  LNTA7002NT1G_SC89-3  [2N7002KTB_SOT523-3]  140.21 81.88 270 top
R1  0_0201_5%  [R_0201]  116.87 14.53 90 bottom
R3  1M_0402_5%~D  [R_0402]  66.27 24.25 270 top
R93  0_0603_5%  [R0603_0OHM]  65.82 89.43 90 top
R95  0_0603_5%  [R0603_0OHM]  68.87 89.43 90 top
R115  80.6_0402_1%  [R_0402]  68.47 92.41 0 top
R116  470K_0402_1%  [R_0402]  68.93 97.31 270 top
R130  47K_0201_5%  [R_0201]  15.98 79.11 0 top
R164  0_0402_5%  [R_0402]  37.56 88.93 270 top
R165  1M_0201_1%  [R_0201]  43.98 87.93 90 bottom
R166  100K_0201_5%  [R_0201]  38.16 89.24 0 bottom
R207  0_0603_5%  [R_0603]  69.74 16.19 270 bottom
R208  0_0603_5%  [R0603_0OHM]  70.95 16.19 270 bottom
R222  0_0402_5%  [R0402_0OHM]  156.27 6.46 0 top
R276  10K_0402_5%  [R_0402]  71.08 22.66 90 top
R277  100K_0201_1%  [R_0201]  66.42 22.15 180 top
R370  0_0402_5%  [R_0402]  68.93 17.33 90 bottom
R373  0_0402_5%  [R_0402]  65.06 19.21 270 bottom
R530  200_0201_1%  [R_0201]  27.66 22.92 270 bottom
R531  200_0201_1%  [R_0201]  28.93 22.92 270 bottom
R532  200_0201_1%  [R_0201]  25.56 20.5 270 bottom
R1090  100K_0402_5%~D  [R_0402]  66.07 19.11 90 bottom
R1194  10K_0201_5%  [R_0201]  85.58 7.02 270 bottom
R1206  0_0402_5%~D  [R_0402]  67.27 19.03 0 bottom
R1207  0_0402_5%~D  [R_0402]  67.27 19.79 0 bottom
R1314  0.01_0603_1%  [R_0603]  138.36 85.63 90 top
R1319  0_0603_5%  [R0603_0OHM]  60.17 71.08 270 bottom
R1320  100K_0201_5%  [R_0201]  58.37 68.66 180 bottom
R1321  21.5K_0402_1%  [R_0402]  59.09 71.09 270 bottom
R1322  10K_0402_1%  [R_0402]  59.09 69.31 270 bottom
R1323  0_0201_5%  [R0201_0OHM]  53.15 68.54 0 bottom
R2741  100K_0402_5%  [R_0402]  16.94 26.75 180 top
R2743  0_0603_5%  [R0603_0OHM]  16.42 32.21 180 top
R5822  0_0201_5%  [R_0201]  102.47 2.37 270 bottom
R5823  0_0402_5%  [R0402_0OHM]  130.03 4.93 270 top
R5824  0_0402_5%  [R0402_0OHM]  129.02 4.93 270 top
R5827  0_0201_5%  [R0201_0OHM]  62.35 20.15 0 top
R5828  0_0201_5%  [R0201_0OHM]  87.58 2.95 270 bottom
R5829  0_0201_5%  [R_0201]  88.16 2.95 270 bottom
R5830  0_0402_5%  [R_0402]  66.95 16.5 180 top
R5831  0_0201_5%  [R_0201]  100.33 13.86 0 top
R5832  0_0201_5%  [R0201_0OHM]  99.73 13.9 90 top
R5833  0_0201_5%  [R_0201]  155 6.58 90 bottom
R5834  0_0201_5%  [R0201_0OHM]  102.5 22.43 180 bottom
R5835  0_0201_5%  [R_0201]  103.12 22.43 0 bottom
R5836  0_0402_5%  [R_0402]  157.12 19.77 0 top
R5837  0_0201_5%  [R_0201]  155.58 7.58 0 bottom
R5838  0_0402_5%  [R0402_0OHM]  32.36 13.3 270 bottom
R5839  0_0402_5%  [R0402_0OHM]  33.18 13.3 270 bottom
R5840  100K_0402_5%  [R_0402]  66.71 83.64 90 top
R5841  0_0201_5%  [R0201_0OHM]  157.77 7.16 90 top
R5843  200K _0201_1%  [R_0201]  60.58 77.81 0 top
R5845  200K _0201_1%  [R_0201]  58.75 77.81 180 top
R5846  100_0402_1%  [R_0402]  50 50.76 0 top
R5847  200K _0201_1%  [R_0201]  50.62 54.63 180 top
R5848  2_1206_5%  [R_1206]  60.61 70.88 90 top
R5849  0_0201_5%  [R_0201]  157.2 7.16 90 top
R5850  2_1206_5%  [R_1206]  58.14 70.88 90 top
R5851  0_0402_5%  [R0402_0OHM]  68.68 19.02 270 top
R5852  0_0201_5%  [R0201_0OHM]  75.84 9.61 180 bottom
R5853  0_0201_5%  [R_0201]  75.84 10.18 180 bottom
R5854  0_0201_5%  [R0201_0OHM]  76.88 9.61 0 bottom
R5855  0_0201_5%  [R_0201]  76.88 10.18 0 bottom
R5858  1M_0402_5%  [R_0402]  5.76 11.04 90 bottom
R5859  4.7K_0805_5%  [R_0805]  5.89 10.08 270 bottom
R5860  4.7M_0402_5%  [R_0402]  2.43 12.05 0 bottom
R5861  0_0201_5%  [R_0201]  99.48 16.39 0 top
R5862  0_0201_5%  [R_0201]  75.59 2.67 270 bottom
R5863  0_0201_5%  [R0201_0OHM]  75 2.67 270 bottom
R5864  0_0201_5%  [R0201_0OHM]  123.29 18.3 180 top
R5865  0_0201_5%  [R_0201]  8.27 15.91 0 bottom
R5867  1M_0201_1%  [R_0201]  141.37 82.89 0 top
R5868  100K_0201_5%  [R_0201]  141.94 82.12 180 top
R5869  0_0201_5%  [R_0201]  101.88 2.37 270 bottom
R5870  0_0201_5%  [R_0201]  103.04 2.37 270 bottom
RC9  1K_0201_5%  [R_0201]  146.34 78.6 180 top
RC10  100K_0201_5%  [R_0201]  30.58 21.55 90 top
RC11  51_0201_5%  [R_0201]  30.43 28.75 90 bottom
RC13  51_0201_5%  [R_0201]  32.37 28.73 90 bottom
RC14  100_0402_1%  [R_0402]  90.84 88.52 90 bottom
RC16  51_0201_5%  [R_0201]  31.68 28.75 90 bottom
RC20  121_0402_1%  [R_0402]  92.62 88.52 90 bottom
RC21  1K_0201_5%  [R_0201]  17.5 54.78 90 bottom
RC26  121_0402_1%  [R_0402]  91.73 88.52 90 bottom
RC32  470_0402_5%  [R_0402]  25.83 42.5 180 top
RC33  0_0402_5%  [R0402_0OHM]  24.91 41.61 0 top
RC35  51_0201_5%  [R_0201]  142.44 81.49 180 top
RC44  1K_0201_5%  [R_0201]  18.04 51.01 180 bottom
RC101  0_0402_5%  [R_0402]  29.89 21.8 180 top
RC102  10K_0201_5%  [R_0201]  26.64 23.87 270 top
RC183  499_0402_1%  [R_0402]  54.52 98.14 270 top
RC184  499_0402_1%  [R_0402]  53.63 98.14 270 top
RC384  0_0402_1%  [R0402_0OHM]  27.87 51.34 270 top
RC386  0_0402_1%  [R0402_0OHM]  27.01 50.43 90 top
RC387  10K_0402_5%  [R_0402]  28.11 21.8 180 top
RC394  10K_0402_5%  [R_0402]  17.17 41.17 0 top
RC395  100K_0201_5%  [R_0201]  17.74 37.17 0 top
RC396  100K_0201_5%  [R_0201]  55.89 10.63 180 bottom
RC397  10K_0402_5%  [R_0402]  54.89 14.58 0 bottom
RD17  10K_0402_5%  [R_0402]  87.04 14.94 0 bottom
RD18  0_0402_5%  [R_0402]  87.93 19.39 180 bottom
RD19  10K_0402_5%  [R_0402]  87.93 18.5 180 bottom
RD20  0_0402_5%  [R_0402]  88.06 21.67 180 bottom
RD58  0_0402_5%  [R0402_0OHM]  95.6 24.42 270 top
RD59  10K_0402_5%  [R_0402]  96.49 24.42 270 top
RD60  0_0402_5%  [R_0402]  87.94 6.67 180 bottom
RD157  240_0402_1%  [R_0402]  130.27 100.27 90 top
RD158  240_0402_1%  [R_0402]  119.8 100.3 270 top
RD159  24.9_0402_1%  [R_0402]  138.16 89.68 270 top
RD160  1.8K_0402_1%  [R_0402]  141.63 96.77 0 top
RD161  2.7_0402_1%  [R_0402]  142.53 94.05 90 top
RD162  1.8K_0402_1%  [R_0402]  142.54 95.88 180 top
RD163  240_0402_1%  [R_0402]  130.26 100.82 90 bottom
RD164  240_0402_1%  [R_0402]  140.74 98.04 270 bottom
RD166  36_0201_1%  [R_0201]  137.16 110.32 0 bottom
RD167  36_0201_1%  [R_0201]  141.39 105.76 0 top
RD168  36_0201_1%  [R_0201]  142.56 106.32 0 top
RD169  36_0201_1%  [R_0201]  142.56 105.2 0 top
RD170  36_0201_1%  [R_0201]  141.39 105.2 0 top
RD171  36_0201_1%  [R_0201]  138.95 110.32 180 bottom
RD172  36_0201_1%  [R_0201]  142.56 105.76 0 top
RD173  36_0201_1%  [R_0201]  133.54 110.32 0 bottom
RD174  36_0201_1%  [R_0201]  135.33 110.32 180 bottom
RD175  36_0201_1%  [R_0201]  141.39 106.32 0 top
RD176  36_0201_1%  [R_0201]  142.55 109.49 0 bottom
RD177  36_0201_1%  [R_0201]  141.39 106.87 0 top
RD178  36_0201_1%  [R_0201]  142.56 104.64 0 top
RD179  36_0201_1%  [R_0201]  131.12 110.32 0 bottom
RD180  36_0201_1%  [R_0201]  142.55 108.35 0 bottom
RD181  36_0201_1%  [R_0201]  142.55 108.92 0 bottom
RD182  36_0201_1%  [R_0201]  142.72 107.44 270 bottom
RD183  36_0201_1%  [R_0201]  142.76 111.13 270 bottom
RD184  36_0201_1%  [R_0201]  142.19 111.13 270 bottom
RD185  36_0201_1%  [R_0201]  140.59 102.25 270 top
RD186  36_0201_1%  [R_0201]  140.59 102.89 90 top
RD187  36_0201_1%  [R_0201]  141.39 103.52 0 top
RD188  36_0201_1%  [R_0201]  142.56 103.52 0 top
RD189  36_0201_1%  [R_0201]  142.97 105.64 90 bottom
RD190  36_0201_1%  [R_0201]  141.39 104.08 0 top
RD191  36_0201_1%  [R_0201]  142.56 104.08 0 top
RD192  36_0201_1%  [R_0201]  132.91 110.32 180 bottom
RD193  49.9_0201_1%  [R_0201]  119.22 105.49 0 bottom
RD194  240_0402_1%  [R_0402]  93.89 100.3 270 top
RD195  240_0402_1%  [R_0402]  104.37 100.87 270 top
RD196  240_0402_1%  [R_0402]  114.83 100.3 0 bottom
RD197  240_0402_1%  [R_0402]  104.38 101.14 270 bottom
RD198  36_0201_1%  [R_0201]  93.19 106.94 180 top
RD199  36_0201_1%  [R_0201]  93.19 103.59 180 bottom
RD200  36_0201_1%  [R_0201]  93.19 104.71 180 top
RD201  36_0201_1%  [R_0201]  93.19 103.59 180 top
RD202  49.9_0201_1%  [R_0201]  114.89 105.26 90 bottom
RD203  36_0201_1%  [R_0201]  93.19 104.71 180 bottom
RD204  36_0201_1%  [R_0201]  93.19 106.94 180 bottom
RD205  36_0201_1%  [R_0201]  93.19 105.83 180 top
RD206  36_0201_1%  [R_0201]  93.19 107.5 180 bottom
RD207  36_0201_1%  [R_0201]  92.04 104.16 90 top
RD208  36_0201_1%  [R_0201]  93.19 108.81 180 bottom
RD209  36_0201_1%  [R_0201]  93.19 105.83 180 bottom
RD210  36_0201_1%  [R_0201]  93.19 105.27 180 top
RD211  36_0201_1%  [R_0201]  93.19 107.5 180 top
RD212  36_0201_1%  [R_0201]  92.04 106.24 90 bottom
RD213  36_0201_1%  [R_0201]  93.19 106.39 180 top
RD214  36_0201_1%  [R_0201]  93.19 108.25 180 bottom
RD215  36_0201_1%  [R_0201]  93.19 108.62 180 top
RD216  36_0201_1%  [R_0201]  92.04 108.57 90 bottom
RD217  36_0201_1%  [R_0201]  92.04 108.61 270 top
RD218  36_0201_1%  [R_0201]  93.19 106.39 180 bottom
RD219  36_0201_1%  [R_0201]  92.04 105.92 270 top
RD220  36_0201_1%  [R_0201]  93.19 104.15 180 top
RD221  36_0201_1%  [R_0201]  93.19 109.37 180 bottom
RD222  36_0201_1%  [R_0201]  93.19 104.15 180 bottom
RD223  36_0201_1%  [R_0201]  93.19 105.27 180 bottom
RD224  36_0201_1%  [R_0201]  93.19 108.06 180 top
RD225  36_0201_1%  [R_0201]  93.19 103.02 180 top
RD226  1.8K_0402_1%  [R_0402]  116.62 104.53 90 top
RD227  1.8K_0402_1%  [R_0402]  115.73 105.44 270 top
RD228  2.7_0402_1%  [R_0402]  135.47 78.44 0 bottom
RD229  24.9_0402_1%  [R_0402]  134.59 80.21 90 bottom
RD230  240_0402_1%  [R_0402]  130.29 98.63 90 top
RD231  240_0402_1%  [R_0402]  119.8 97.72 90 top
RD232  240_0402_1%  [R_0402]  140.75 95.47 90 bottom
RD233  240_0402_1%  [R_0402]  130.29 100.08 270 bottom
RD234  240_0402_1%  [R_0402]  104.37 98.32 90 top
RD235  240_0402_1%  [R_0402]  93.89 97.73 90 top
RD236  240_0402_1%  [R_0402]  115.76 99.47 180 bottom
RD237  240_0402_1%  [R_0402]  104.37 98.57 90 bottom
RD238  0_0201_5%  [R_0201]  140.65 100.44 0 top
RD239  0_0201_5%  [R_0201]  140.65 101.02 0 top
RD240  0_0201_5%  [R_0201]  130.3 103.82 270 top
RD241  0_0201_5%  [R_0201]  130.3 104.43 90 top
RD242  0_0201_5%  [R_0201]  130.3 104.21 270 bottom
RD243  0_0201_5%  [R_0201]  130.3 104.81 90 bottom
RD244  0_0201_5%  [R_0201]  119.74 103.04 90 bottom
RD245  0_0201_5%  [R_0201]  119.76 102.42 270 bottom
RD246  0_0201_5%  [R_0201]  114.75 103.23 90 top
RD247  0_0201_5%  [R_0201]  114.75 102.65 0 top
RD248  0_0201_5%  [R_0201]  104.38 103.93 270 top
RD249  0_0201_5%  [R_0201]  104.38 104.53 90 top
RD250  0_0201_5%  [R_0201]  104.4 103.61 270 bottom
RD251  0_0201_5%  [R_0201]  104.39 104.24 90 bottom
RD252  0_0201_5%  [R_0201]  93.91 102.94 270 bottom
RD253  0_0201_5%  [R_0201]  93.91 103.54 90 bottom
RE1  10K_0402_5%  [R_0402]  139.04 28.1 270 top
RE2  100K_0402_5%  [R_0402]  134.53 28.15 0 top
RE3  10K_0402_5%  [R_0402]  137.05 28.28 0 top
RE6  10K_0402_5%  [R_0402]  139.04 29.09 90 top
RE7  100K_0402_5%  [R_0402]  134.53 29.29 0 top
RE8  10K_0402_5%  [R_0402]  137.05 29.17 0 top
RE10  0_0402_5%  [R_0402]  29 11.51 180 bottom
RE11  0_0603_5%  [R_0603]  23.21 19.3 0 top
RE12  0_0402_5%  [R0402_0OHM]  29 12.4 180 bottom
RE14  10K_0402_5%  [R_0402]  18.18 7.83 0 bottom
RE15  0_0603_5%  [R0603_0OHM]  29.31 18.24 180 bottom
RE17  0_0402_5%  [R_0402]  23.66 17.07 270 bottom
RE18  33_0402_5%  [R_0402]  18.18 14.05 0 bottom
RE19  33_0402_5%  [R_0402]  18.18 12.27 0 bottom
RE21  33_0402_5%  [R_0402]  18.18 10.5 0 bottom
RE22  0_0402_5%  [R0402_0OHM]  18.18 11.39 0 bottom
RE23  10K_0402_5%  [R_0402]  21.75 17.07 270 bottom
RE27  4.7K_0402_5%  [R_0402]  29 14.18 180 bottom
RE29  10K_0402_5%  [R_0402]  28.09 13.29 0 bottom
RE31  33_0402_5%  [R_0402]  19.1 9.54 180 bottom
RE48  100K_0201_1%  [R_0201]  43.25 12 90 bottom
RE105  2.2K_0201_5%  [R_0201]  43.02 19.6 90 top
RE106  0_0402_5%  [R0402_0OHM]  38.15 19.13 180 top
RE107  2.2K_0201_5%  [R_0201]  43.6 19.6 90 top
RE108  100K_0201_5%  [R_0201]  52.76 16.08 0 top
RE109  100K_0201_5%  [R_0201]  35.87 13.67 0 top
RE111  2.2K_0201_5%  [R_0201]  40.55 4.69 270 top
RE112  2.2K_0201_5%  [R_0201]  39.91 4.69 270 top
RE113  100_0402_1%  [R_0402]  39.34 13.62 270 bottom
RE115  43K_0402_1%  [R_0402]  42.39 4.2 90 top
RE119  100K_0201_5%  [R_0201]  53.15 5.92 0 top
RE124  10K_0201_5%  [R_0201]  52.76 16.72 0 top
RE125  300_0402_5%  [R_0402]  37.64 7.45 180 top
RE126  300_0402_5%  [R_0402]  35.86 10.75 180 top
RE127  10K_0201_5%  [R_0201]  52.04 5.2 270 top
RE130  100K_0201_5%  [R_0201]  52.76 15.45 0 top
RE132  0_0201_5%  [R0201_0OHM]  46.26 4.55 90 top
RE133  100K_0201_5%  [R_0201]  37.98 15.2 180 top
RE137  100K_0201_5%  [R_0201]  35.82 15.83 180 top
RE142  100K_0201_5%  [R_0201]  35.82 16.47 180 top
RE147  0_0402_5%  [R_0402]  53.9 8.72 180 top
RE150  47K_0201_5%  [R_0201]  10.06 64.28 0 bottom
RE153  33_0402_5%  [R_0402]  52.98 6.81 0 top
RE154  100K_0402_5%  [R_0402]  38.15 16.95 180 top
RE155  10K_0201_5%  [R_0201]  43.15 3.8 270 top
RE156  100K_0201_5%  [R_0201]  54.03 10.88 0 top
RE157  100K_0201_5%  [R_0201]  35.57 12.4 180 top
RE158  100_0201_1%  [R_0201]  52.76 10.88 0 top
RE159  10K_0201_5%  [R_0201]  35.89 9.99 180 top
RE160  100K_0201_5%  [R_0201]  39.09 5.2 270 top
RE161  100K_0201_5%  [R_0201]  37.98 17.61 180 top
RE162  100K_0201_5%  [R_0201]  46.83 5.14 270 top
RE164  100_0201_1%  [R_0201]  52.8 11.79 90 top
RE172  33_0402_5%  [R_0402]  25.74 23.64 0 bottom
RE177  0_0201_5%  [R0201_0OHM]  43.15 5.2 270 top
RE178  0_0201_5%  [R0201_0OHM]  41.92 19.51 180 top
RE180  0_0201_5%  [R0201_0OHM]  32.09 12.02 180 top
RE183  10K_0201_5%  [R_0201]  33.08 11.13 0 top
RE184  100K_0201_5%  [R_0201]  35.24 17.1 0 top
RE185  0_0201_5%  [R0201_0OHM]  51.41 5.2 270 top
RE187  1K_0201_5%  [R_0201]  35.82 17.74 180 top
RE193  0_0402_5%  [R_0402]  30.77 8.1 270 top
RE194  4.3K_0402_5%  [R_0402]  55.6 9.86 180 top
RE196  240K_0402_5%  [R_0402]  35.14 13.28 180 top
RE199  1.58K_0402_1%  [R_0402]  52.92 19.45 0 top
RE200  0_0201_5%  [R0201_0OHM]  56.27 7.07 180 bottom
RE201  10K_0201_5%  [R_0201]  50.22 2.11 0 top
RE202  10K_0201_5%  [R_0201]  47.66 3.03 90 top
RE203  10K_0201_5%  [R_0201]  47.49 5.35 0 top
RE204  10K_0201_5%  [R_0201]  48.8 3.03 90 top
RE205  10K_0201_5%  [R_0201]  49.37 3.61 270 top
RE206  0_0201_5%  [R_0201]  48.23 3.03 90 top
RE209  0_0201_5%  [R0201_0OHM]  49.41 5.35 180 top
RE215  8.2K_0201_5%  [R_0201]  37.27 11.04 0 top
RE219  2.2K_0201_5%  [R_0201]  32.95 17.23 0 top
RE222  0_0201_5%  [R0201_0OHM]  31.68 17.23 0 top
RE227  2.2K_0201_5%  [R_0201]  37.98 19.89 180 top
RE228  2.2K_0201_5%  [R_0201]  37.98 20.53 180 top
RE244  100K_0201_5%  [R_0201]  35.82 15.2 180 top
RE245  0_0201_5%  [R0201_0OHM]  45.69 5.14 270 top
RE247  100K_0201_5%  [R_0201]  37.98 14.56 180 top
RE248  0_0402_5%  [R0402_0OHM]  52.73 17.48 0 top
RE251  1K_0402_5%  [R_0402]  37.23 16.19 0 top
RE252  0_0201_5%  [R0201_0OHM]  34.35 12.59 180 top
RE259  0_0201_5%  [R0201_0OHM]  50.52 4.62 90 top
RE260  0_0201_5%  [R0201_0OHM]  55.89 10.88 180 top
RE263  0_0402_5%  [R0402_0OHM]  34.64 10.7 270 bottom
RE264  100K_0201_5%  [R_0201]  45.69 3.87 270 top
RE265  10K_0201_5%  [R_0201]  35.87 13.09 0 top
RE266  100K_0201_5%  [R_0201]  52.76 14.81 0 top
RE267  100K_0201_5%  [R_0201]  52.76 14.18 0 top
RE268  100K_0201_5%  [R_0201]  52.76 13.54 0 top
RE269  100K_0201_5%  [R_0201]  53.15 4.65 0 top
RE270  100K_0201_5%  [R_0201]  53.15 5.29 0 top
RE271  0_0402_5%  [R_0402]  29 15.07 180 bottom
RE272  0_0603_5%  [R_0603]  30.13 12.4 90 bottom
RE274  0_0201_5%  [R0201_0OHM]  35.95 7.58 180 top
RE275  0_0201_5%  [R0201_0OHM]  35.95 8.21 180 top
RE276  2.2K_0201_5%  [R_0201]  45.12 19.54 90 top
RE277  2.2K_0201_5%  [R_0201]  44.55 19.54 90 top
RE278  10K_0201_5%  [R_0201]  54.71 8.34 0 top
RE279  100K_0201_5%  [R_0201]  54.71 8.97 0 top
RE288  0_0201_5%  [R_0201]  37.26 9.1 180 top
RE289  1.5K_0201_5%  [R_0201]  45.97 21.16 0 top
RE290  1.5K_0201_5%  [R_0201]  41.94 23.98 90 top
RE291  100K_0201_5%  [R_0201]  33.66 20.15 180 top
RE292  10K_0402_5%  [R_0402]  31.71 13.73 0 top
RE293  100K_0201_5%  [R_0201]  38.49 31.45 180 top
RE294  100K_0201_5%  [R_0201]  34.73 24.59 0 top
RE295  0_0201_5%  [R0201_0OHM]  69.4 82.24 90 bottom
RE296  0_0201_5%  [R0201_0OHM]  100.02 23.77 0 top
RE297  0_0201_5%  [R_0201]  15.38 21.42 180 top
RE299  0_0201_5%  [R_0201]  27.02 18.98 270 bottom
RE300  10K_0201_5%  [R_0201]  59.62 9.54 0 top
RE426  10K_0201_5%  [R_0201]  43.82 12 90 bottom
RE427  100K_0201_5%  [R_0201]  45.12 4.55 90 top
RE428  0_0402_5%  [R_0402]  25.74 21.86 0 bottom
RE429  0_0201_5%  [R0201_0OHM]  44.99 3.28 90 top
RE430  0_0201_5%  [R0201_0OHM]  46.19 10.51 180 bottom
